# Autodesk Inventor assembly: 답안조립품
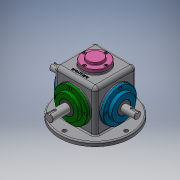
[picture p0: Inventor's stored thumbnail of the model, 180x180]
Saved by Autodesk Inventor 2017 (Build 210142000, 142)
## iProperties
Part Number: 답안조립품
Material: 일반
Document SubType Name: Assembly
Designer: 00-00
Mass: 3167.92 g
Surface Area: 2695.22 cm^2
Volume: 839.977 cm^3
Density: 3.77143 g/cm^3
Author: 00-00
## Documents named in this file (15)
- C:\Users\00-00\Desktop\601004V1017\답안조립품.iam
- C:\Users\00-00\Desktop\601004V1017\본체.ipt
- C:\Users\00-00\Desktop\601004V1017\메인베벨기어.ipt
- C:\Users\00-00\Desktop\601004V1017\메인축.ipt
- C:\Users\00-00\Desktop\601004V1017\메인커버.ipt
- C:\Users\00-00\Desktop\601004V1017\베어링 6203.ipt
- C:\Users\00-00\Desktop\601004V1017\베어링 6204.ipt
- C:\Users\00-00\Desktop\601004V1017\볼트 M4.ipt
- C:\Users\00-00\Desktop\601004V1017\상부커버.ipt
- C:\Users\00-00\Desktop\601004V1017\서브베벨기어.ipt
- C:\Users\00-00\Desktop\601004V1017\서브축.ipt
- C:\Users\00-00\Desktop\601004V1017\서브커버.ipt
- C:\Users\00-00\Desktop\601004V1017\오일 실 17 32 8.ipt
- C:\Users\00-00\Desktop\601004V1017\오일 실 20 35 8.ipt
- C:\Users\00-00\Desktop\601004V1017\키 4x4.ipt
## Named parameters: d10_d8 = 0, d11_d9 = 0
